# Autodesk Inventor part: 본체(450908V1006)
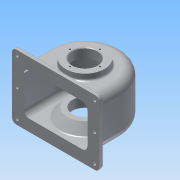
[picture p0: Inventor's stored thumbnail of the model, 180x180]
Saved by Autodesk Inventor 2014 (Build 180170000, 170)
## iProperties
Created: 2015-09
Part Number: 본체(450908V1006)
Material: 알루미늄 6061
Document SubType Name: Modeling
Designer: imci
Density: 2.71 g/cm^3
Appearance: 알루미늄 - 평지
Mass: 723.36 g
Surface Area: 891.865 cm^2
Volume: 266.923 cm^3
Author: imci
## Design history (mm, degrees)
sketch "스케치1"
  geometry: L1 (-70, 52)-(70, 52); L2 (70, 52)-(70, -52); L3 (70, -52)-(-70, -52); L4 (-70, -52)-(-70, 52); L5 (-70, 52)-(70, -52); 2 further points
  constraints: 10 end point, 2 parallel, 1 coincident, 1 horizontal, 1 midpoint, 1 perpendicular
  dimensions: "d0" = 140 distance of L1.start L1.end; "d1" = 104 distance of L1.end L2.end
extrude "돌출1" new body sketch "스케치1" distance "d2" = 7; taper "d3" = 0 deg
sketch "스케치2"
  geometry: L1 (-70, 0)-(70, 0) reference; L2 (70, 0)-(70, 7) reference; L3 (-70, 7)-(70, 7) reference; L4 (-70, 0)-(-70, 7) reference; L5 (-70, 0)-(70, 0) reference; L6 (-57, 47)-(-57, 7); L7 (57, 47)-(57, 7); A1 r 57 centre (0, 47) between (57, 47) and (-57, 47); 2 further points
  constraints: 4 end point, 2 perpendicular, 2 point on circle, 2 point on line, 2 tangent, 1 centre point, 1 midpoint, 1 vertical alignment
  dimensions: "d4" = 114 diameter of A1; "d5" = 47 distance of point (0, 0) A1.centre
extrude "돌출2" join sketch "스케치2" stored distance "d6" = 77; taper "d7" = 0 deg
sketch "스케치3"
  geometry: C1 r 31 at (0, 47); A1 r 57 centre (0, 47) between (57, 47) and (-57, 47) reference; 1 further point
  constraints: 1 centre point, 1 coincident
  dimensions: "d8" = 62 diameter of C1
extrude "돌출3" join sketch "스케치3" distance "d9" = 10; taper "d10" = 0 deg
sketch "스케치4"
  geometry: L1 (0, 0)-(0, 24); L2 (0, 0)-(24, 0); L3 (0, 0)-(0, -24); L4 (0, 0)-(-24, 0); C1 r 31 at (0, 0) reference; A1 r 24 centre (0, 0) between (0, 24) and (24, 0); 5 further points
  constraints: 8 end point, 5 coincident, 4 point on circle, 3 perpendicular, 1 centre point, 1 vertical
  dimensions: "d11" = 48 diameter of A1
hole "구멍1" sketch "스케치4" at (0, 24), (24, 0), (0, -24), (-24, 0) diameter "d12" = 2.459; stored, may be unused: countersink angle "d16" = 90 deg, drill point angle "d18" = 118 deg; dims "d13" = 6, "d14" = 4, "d15" = 2, "d17" = 8
sketch "스케치5"
  geometry: L1 (-57, 47)-(-57, 7) reference; L2 (57, 7)-(57, 47) reference; L3 (-70, 0)-(70, 0) reference; L4 (70, 0)-(70, 7) reference; L5 (-70, 7)-(70, 7) reference; L6 (-70, 0)-(-70, 7) reference; L7 (-51, 0)-(-51, 47); L8 (51, 47)-(51, 0); L9 (-51, 0)-(51, 0); A1 r 57 centre (0, 47) between (57, 47) and (-57, 47) reference; A2 r 51 centre (0, 47) between (51, 47) and (-51, 47); 1 further point
  constraints: 6 end point, 2 point on circle, 2 point on line, 1 centre point, 1 collinear
  dimensions: "d19" = 6 radial gap between concentric circles of A2 A1; "d20" = 6 distance between parallel lines of L8 L2; "d21" = 6 distance between parallel lines of L1 L7
extrude "돌출4" cut sketch "스케치5" stored distance "d22" = 67; taper "d23" = 0 deg
node "작업 평면2"
sketch "스케치9"
  geometry: C1 r 28 at (0, 47); A1 r 57 centre (0, 47) between (57, 47) and (-57, 47) reference; 1 further point
  constraints: 1 centre point, 1 coincident
  dimensions: "d31" = 56 diameter of C1
extrude "돌출6" join sketch "스케치9" stored distance "d32" = 67; taper "d33" = 40 deg
sketch "스케치12"
  geometry: L1 (75, -19.5)-(86.747, -33.5) reference; L2 (80.22, -33.5)-(84.416, -38.5); L3 (47, -38.5)-(47, 38.5) reference; L4 (47, 38.5)-(47, 38.5) reference; L5 (47, -38.5)-(47, 38.5) reference; L6 (47, -38.5)-(47, -38.5) reference; L7 (47, -38.5)-(104, -38.5) reference; L8 (47, -33.5)-(98, -33.5) reference; L9 (80.22, -33.5)-(47, -33.5); L10 (47, -38.5)-(84.416, -38.5); 1 further point
  constraints: 6 end point, 2 parallel, 2 point on line, 1 perpendicular
  dimensions: "d38" = 5 distance between parallel lines of L2 L1
revolve "회전2" sketch "스케치12" stored, may be unused: angle "d39" = 90 deg
sketch "스케치13"
  geometry: C1 r 33.22 at (0, 0) reference; C2 r 33 at (0, 0); 1 further point
  constraints: 1 centre point, 1 coincident
  dimensions: "d40" = 66 diameter of C2
extrude "돌출7" join sketch "스케치13" distance "d41" = 2; taper "d42" = 0 deg
sketch "스케치14"
  geometry: L1 (0, 0)-(0, 28); L2 (0, 0)-(-28, 0); L3 (0, 0)-(0, -28); L4 (0, 0)-(28, 0); C1 r 33 at (0, 0) reference; A1 r 28 centre (0, 0) between (0, 28) and (-28, 0); 5 further points
  constraints: 8 end point, 5 coincident, 4 point on circle, 3 perpendicular, 1 centre point, 1 vertical
  dimensions: "d43" = 56 diameter of A1
hole "구멍2" sketch "스케치14" at (0, 28), (-28, 0), (0, -28), (28, 0) diameter "d44" = 2.459; stored, may be unused: countersink angle "d48" = 90 deg, drill point angle "d50" = 118 deg; dims "d45" = 7, "d46" = 4, "d47" = 2, "d49" = 9
sketch "스케치15"
  geometry: C1 r 33 at (0, 0) reference; C2 r 20 at (0, 0); 1 further point
  constraints: 1 centre point, 1 coincident
  dimensions: "d51" = 40 diameter of C2
extrude "돌출8" cut sketch "스케치15" stored distance "d52" = 2; taper "d53" = 0 deg
node "작업 평면3"
sketch "스케치16"
  geometry: C1 r 6 at (0, 0); 1 further point
  constraints: 1 centre point, 1 coincident
  dimensions: "d55" = 12 diameter of C1
extrude "돌출9" join sketch "스케치16" stored distance "d56" = 2; taper "d57" = 10 deg
sketch "스케치17"
  geometry: C1 r 6 at (0, 0) reference; 1 further point
  constraints: 1 coincident
hole "구멍3" sketch "스케치17" at (0, 0) diameter "d58" = 4.459; stored, may be unused: countersink angle "d62" = 90 deg, drill point angle "d64" = 0 deg; dims "d59" = 7, "d60" = 4, "d61" = 2, "d63" = 9
sketch "스케치18"
  geometry: L1 (70, 52)-(-70, 52) reference; L2 (-70, 52)-(-70, -52) reference; L3 (-70, -52)-(70, -52) reference; 4 further points
  constraints: 2 vertical alignment, 1 horizontal alignment
  dimensions: "d65" = 8 distance from line of L1 point (-62, 44); "d66" = 8 distance from line of L3 point (-62, -44); "d67" = 8 distance from line of L2 point (-62, -44)
hole "구멍4" sketch "스케치18" at (-62, 44), (-62, 0), (-62, -44) diameter "d68" = 5; stored, may be unused: countersink angle "d72" = 90 deg, drill point angle "d74" = 0 deg; dims "d69" = 7, "d70" = 4, "d71" = 2, "d73" = 9
fillet "모깎기2" dims "d75" = 7
fillet "모깎기3" dims "d76" = 14
fillet "모깎기4" dims "d77" = 9
fillet "모깎기5" dims "d78" = 3
fillet "모깎기6" dims "d79" = 0.5
chamfer "모따기1" distance "d80" = 1; stored, may be unused: second distance "d81" = 2, angle "d82" = 45 deg
fillet "모깎기7" dims "d83" = 1
sketch "스케치19"
  geometry: L1 (-14, 0)-(-14, -39) reference; L2 (-20.5, -47)-(69.5, -47) reference; 2 further points
  constraints: 1 other
  dimensions: "d84" = 38.5 distance from line of L1 point (24.5, -17); "d85" = 30 distance from line of L2 point (24.5, -17)
feature "엠보싱1" sketch "스케치19" dims "d0" = 140, "d1" = 104, "d86" = 0.5, "d87" = 0
fillet "모깎기8" dims "d88" = 0.5
node "솔리드1"
mirror "대칭1"
node "투영된 루프1"
node "투영된 루프2"
node "투영된 루프3"
other parameters: "d30" = -19
